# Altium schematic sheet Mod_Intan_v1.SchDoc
size A4
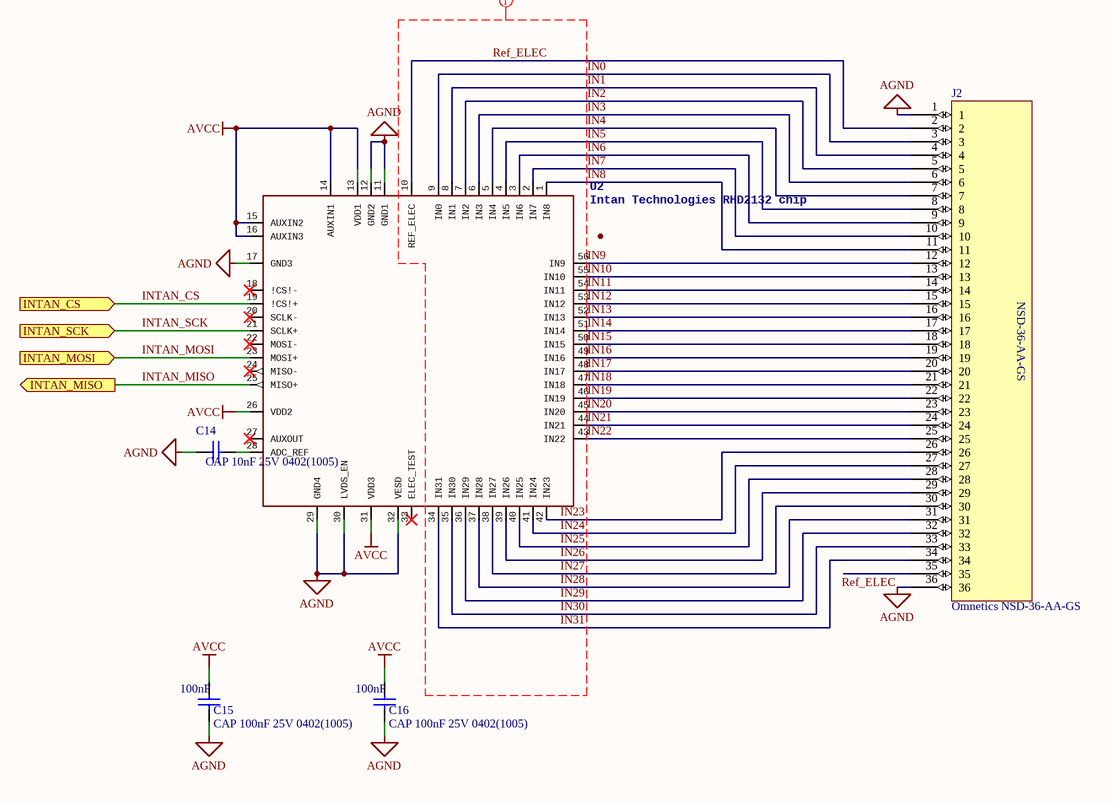
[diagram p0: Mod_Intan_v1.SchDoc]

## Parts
C14  CAP 10nF 25V 0402(1005)  [CAPC0402(1005)60_L]
C15  CAP 100nF 25V 0402(1005)  value 100nF  [CAPC0402(1005)60_L]
C16  CAP 100nF 25V 0402(1005)  value 100nF  [CAPC0402(1005)60_L]
J2  Omnetics NSD-36-AA-GS  [NSD-36-AA-GS]
U2  Intan Technologies RHD2132 chip  [QFN56_large]

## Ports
INTAN_CS (in), INTAN_MISO (out), INTAN_MOSI (in), INTAN_SCK (in)

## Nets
AGND: C14.1 C15.1 C16.1 J2.1 J2.36 U2.11(GND1) U2.12(GND2) U2.17(GND3) U2.29(GND4) U2.30(LVDS_EN) U2.32(VESD)
AVCC: C15.2 C16.2 U2.13(VDD1) U2.14(AUXIN1) U2.15(AUXIN2) U2.16(AUXIN3) U2.26(VDD2) U2.31(VDD3)
IN0: J2.3 U2.9(IN0)
IN1: J2.4 U2.8(IN1)
IN2: J2.5 U2.7(IN2)
IN3: J2.6 U2.6(IN3)
IN4: J2.7 U2.5(IN4)
IN5: J2.8 U2.4(IN5)
IN6: J2.9 U2.3(IN6)
IN7: J2.10 U2.2(IN7)
IN8: J2.11 U2.1(IN8)
IN9: J2.12 U2.56(IN9)
IN10: J2.13 U2.55(IN10)
IN11: J2.14 U2.54(IN11)
IN12: J2.15 U2.53(IN12)
IN13: J2.16 U2.52(IN13)
IN14: J2.17 U2.51(IN14)
IN15: J2.18 U2.50(IN15)
IN16: J2.19 U2.49(IN16)
IN17: J2.20 U2.48(IN17)
IN18: J2.21 U2.47(IN18)
IN19: J2.22 U2.46(IN19)
IN20: J2.23 U2.45(IN20)
IN21: J2.24 U2.44(IN21)
IN22: J2.25 U2.43(IN22)
IN23: J2.26 U2.42(IN23)
IN24: J2.27 U2.41(IN24)
IN25: J2.28 U2.40(IN25)
IN26: J2.29 U2.39(IN26)
IN27: J2.30 U2.38(IN27)
IN28: J2.31 U2.37(IN28)
IN29: J2.32 U2.36(IN29)
IN30: J2.33 U2.35(IN30)
IN31: J2.34 U2.34(IN31)
INTAN_CS: U2.19(!CS!+) ; port INTAN_CS
INTAN_MISO: U2.25(MISO+) ; port INTAN_MISO
INTAN_MOSI: U2.23(MOSI+) ; port INTAN_MOSI
INTAN_SCK: U2.21(SCLK+) ; port INTAN_SCK
Ref_ELEC: J2.2 J2.35 U2.10(REF_ELEC)
NetC14_2: C14.2 U2.28(ADC_REF)

Not connected (* = marked no-connect by the designer): U2 18(!CS!-)* 20(SCLK-)* 22(MOSI-)* 24(MISO-)* 27(AUXOUT)* 33(ELEC_TEST)*

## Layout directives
net class Undefined: IN0, IN1, IN2, IN3, IN4, IN5, IN6, IN7, IN8, IN9, IN10, IN11, IN12, IN13, IN14, IN15, IN16, IN17, IN18, IN19, IN20, IN21, IN22, IN23, IN24, IN25, IN26, IN27, IN28, IN29, IN30, IN31, Ref_ELEC

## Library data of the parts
C14 = CMP-1034-01879-1: CAP 10nF 25V ±5% 0402 (1005 Metric) Thickness 0.6mm SMD; Case-Metric: 1005; Case-EIA: 0402
C15 C16 = CMP-1034-02072-1: CAP 100nF 25V ±10% 0402 (1005 Metric) Thickness 0.6mm SMD; Case-Metric: 1005; Case-EIA: 0402
J2 = Omnetics NSD-36-AA-GS: NSD-36-AA-GS; Part Number: A79025-001
U2 = RHD2132_QFN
